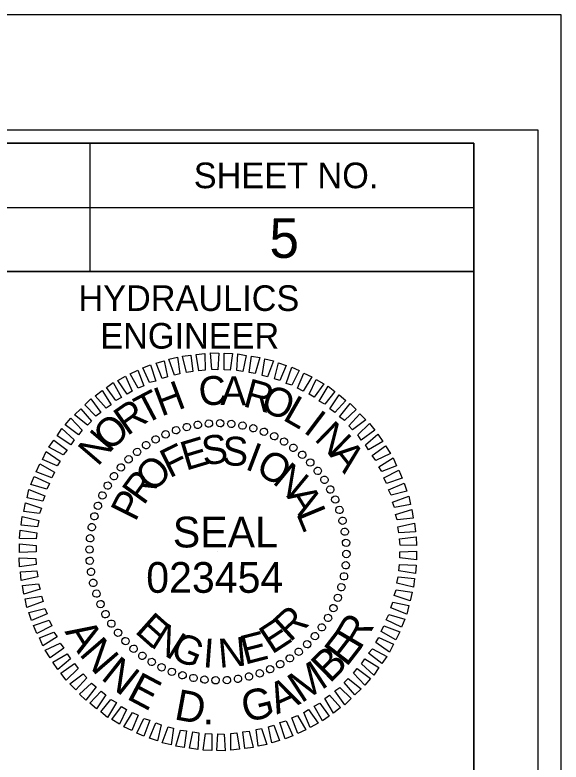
# Model space of a CAD drawing. Extents: x 574125 to 576234, y -56630 to -55530.
# Drawn here: x 575917.2 to 576023.8, y -55675.6 to -55529.8 of the extents above; entities that cross this region are included whole.
import ezdxf

# ---------------------------------------------------------------- set-up
doc = ezdxf.new("R2010")
doc.units = 0
for name, color, linetype in [('Sheet Data Field CELL', 7, 'Continuous'), ('Sheet Plot Border Inside CELL', 7, 'Continuous'), ('Sheet Plot Border Outside CELL', 7, 'Continuous'), ('Sheet Professional Seal CELL', 7, 'Continuous'), ('Sheet Profile CELL', 7, 'Continuous')]:
    doc.layers.add(name, color=color, linetype=linetype)

msp = doc.modelspace()

# ---------------------------------------------------------------- linework, layer by layer
at = {"layer": 'Sheet Plot Border Inside CELL'}
msp.add_lwpolyline([(576019.31, -55552.3), (574352.81, -55552.3), (574352.81, -56607.4), (576019.31, -56607.4)], close=True, dxfattribs=at)
at = {"layer": 'Sheet Plot Border Outside CELL'}
msp.add_lwpolyline([(576023.81, -55529.85), (574339.81, -55529.85), (574339.81, -56629.85), (576023.81, -56629.85)], close=True, dxfattribs=at)
at = {"layer": 'Sheet Professional Seal CELL'}
for p, q in [((575950.72, -55610.24), (575950.72, -55610.24)), ((575952.92, -55609.84), (575952.92, -55609.84)), ((575955.07, -55609.54), (575955.07, -55609.54)), ((575957.27, -55609.49), (575957.27, -55609.49)), ((575959.47, -55609.64), (575959.47, -55609.64)), ((575961.62, -55609.99), (575961.62, -55609.99)), ((575946.62, -55611.64), (575946.62, -55611.64)), ((575948.62, -55610.84), (575948.62, -55610.84)), ((575963.72, -55610.44), (575963.72, -55610.44)), ((575965.82, -55611.14), (575965.82, -55611.14)), ((575944.67, -55612.64), (575944.67, -55612.64)), ((575967.82, -55612.04), (575967.82, -55612.04)), ((575969.77, -55613.04), (575969.77, -55613.04)), ((575942.77, -55613.79), (575942.77, -55613.79)), ((575971.57, -55614.29), (575971.57, -55614.29)), ((575941.02, -55615.04), (575941.02, -55615.04)), ((575973.32, -55615.64), (575973.32, -55615.64)), ((575939.37, -55616.54), (575939.37, -55616.54)), ((575974.87, -55617.14), (575974.87, -55617.14)), ((575937.87, -55618.09), (575937.87, -55618.09)), ((575976.37, -55618.79), (575976.37, -55618.79)), ((575936.52, -55619.84), (575936.52, -55619.84)), ((575977.62, -55620.54), (575977.62, -55620.54)), ((575935.27, -55621.64), (575935.27, -55621.64)), ((575978.77, -55622.44), (575978.77, -55622.44)), ((575934.27, -55623.59), (575934.27, -55623.59)), ((575979.77, -55624.39), (575979.77, -55624.39)), ((575933.37, -55625.59), (575933.37, -55625.59)), ((575980.57, -55626.39), (575980.57, -55626.39)), ((575932.67, -55627.69), (575932.67, -55627.69)), ((575981.17, -55628.49), (575981.17, -55628.49)), ((575932.22, -55629.79), (575932.22, -55629.79)), ((575981.57, -55630.69), (575981.57, -55630.69)), ((575931.87, -55631.94), (575931.87, -55631.94)), ((575981.87, -55632.84), (575981.87, -55632.84)), ((575931.72, -55634.14), (575931.72, -55634.14)), ((575956.82, -55634.59), (575956.82, -55634.59)), ((575981.92, -55635.04), (575981.92, -55635.04)), ((575931.77, -55636.34), (575931.77, -55636.34)), ((575981.77, -55637.24), (575981.77, -55637.24)), ((575932.07, -55638.49), (575932.07, -55638.49)), ((575981.42, -55639.39), (575981.42, -55639.39)), ((575932.47, -55640.69), (575932.47, -55640.69)), ((575980.97, -55641.49), (575980.97, -55641.49)), ((575933.07, -55642.79), (575933.07, -55642.79)), ((575980.27, -55643.59), (575980.27, -55643.59)), ((575933.87, -55644.79), (575933.87, -55644.79)), ((575934.87, -55646.74), (575934.87, -55646.74)), ((575979.37, -55645.59), (575979.37, -55645.59)), ((575978.37, -55647.54), (575978.37, -55647.54)), ((575936.02, -55648.64), (575936.02, -55648.64)), ((575977.12, -55649.34), (575977.12, -55649.34)), ((575937.27, -55650.39), (575937.27, -55650.39)), ((575975.77, -55651.09), (575975.77, -55651.09)), ((575938.77, -55652.04), (575938.77, -55652.04)), ((575974.27, -55652.64), (575974.27, -55652.64)), ((575940.32, -55653.54), (575940.32, -55653.54)), ((575972.62, -55654.14), (575972.62, -55654.14)), ((575942.07, -55654.89), (575942.07, -55654.89)), ((575970.87, -55655.39), (575970.87, -55655.39)), ((575943.87, -55656.14), (575943.87, -55656.14)), ((575968.97, -55656.54), (575968.97, -55656.54)), ((575945.82, -55657.14), (575945.82, -55657.14)), ((575947.82, -55658.04), (575947.82, -55658.04)), ((575965.02, -55658.34), (575965.02, -55658.34)), ((575967.02, -55657.54), (575967.02, -55657.54)), ((575949.92, -55658.74), (575949.92, -55658.74)), ((575952.02, -55659.19), (575952.02, -55659.19)), ((575954.17, -55659.54), (575954.17, -55659.54)), ((575956.37, -55659.69), (575956.37, -55659.69)), ((575958.57, -55659.64), (575958.57, -55659.64)), ((575960.72, -55659.34), (575960.72, -55659.34)), ((575962.92, -55658.94), (575962.92, -55658.94))]:
    msp.add_line(p, q, dxfattribs=at)
for points in [[(575955.62, -55599.04), (575955.37, -55595.79), (575957.02, -55595.84), (575956.82, -55599.09)], [(575958.02, -55599.09), (575958.02, -55595.84), (575959.67, -55595.89), (575959.22, -55599.14)], [(575948.32, -55600.14), (575947.27, -55596.99), (575948.97, -55596.64), (575949.37, -55599.89)], [(575950.72, -55599.59), (575949.92, -55596.39), (575951.57, -55596.24), (575951.92, -55599.44)], [(575953.12, -55599.29), (575952.57, -55596.09), (575954.27, -55595.89), (575954.32, -55599.14)], [(575960.52, -55599.24), (575960.72, -55595.99), (575962.37, -55596.29), (575961.72, -55599.44)], [(575962.92, -55599.64), (575963.37, -55596.44), (575965.02, -55596.69), (575964.12, -55599.79)], [(575965.47, -55600.19), (575965.97, -55596.94), (575967.67, -55597.34), (575966.52, -55600.44)], [(575943.47, -55601.59), (575942.17, -55598.69), (575943.67, -55598.09), (575944.72, -55601.29)], [(575945.92, -55600.79), (575944.77, -55597.79), (575946.32, -55597.34), (575946.97, -55600.44)], [(575967.87, -55600.84), (575968.62, -55597.74), (575970.17, -55598.24), (575968.92, -55601.19)], [(575970.12, -55601.74), (575971.27, -55598.59), (575972.67, -55599.19), (575971.27, -55602.09)], [(575941.27, -55602.64), (575939.67, -55599.84), (575941.22, -55599.14), (575942.37, -55602.19)], [(575972.37, -55602.69), (575973.62, -55599.74), (575975.17, -55600.44), (575973.47, -55603.24)], [(575936.92, -55605.09), (575935.07, -55602.54), (575936.37, -55601.59), (575938.02, -55604.49)], [(575939.12, -55603.84), (575937.27, -55601.14), (575938.82, -55600.34), (575940.07, -55603.24)], [(575974.67, -55603.84), (575976.02, -55600.99), (575977.52, -55601.84), (575975.62, -55604.44)], [(575976.62, -55605.19), (575978.37, -55602.29), (575979.67, -55603.34), (575977.72, -55605.79)], [(575935.02, -55606.59), (575932.87, -55604.19), (575934.22, -55603.14), (575935.97, -55605.94)], [(575978.67, -55606.69), (575980.52, -55603.94), (575981.82, -55605.04), (575979.62, -55607.39)], [(575933.02, -55608.14), (575930.82, -55605.94), (575932.02, -55604.74), (575933.97, -55607.44)], [(575980.57, -55608.24), (575982.62, -55605.64), (575983.82, -55606.84), (575981.52, -55608.99)], [(575931.37, -55609.89), (575928.82, -55607.84), (575930.07, -55606.69), (575932.17, -55609.09)], [(575929.62, -55611.79), (575927.02, -55609.84), (575928.12, -55608.54), (575930.32, -55610.89)], [(575982.37, -55609.99), (575984.52, -55607.64), (575985.72, -55608.84), (575983.12, -55610.79)], [(575984.12, -55611.79), (575986.42, -55609.54), (575987.47, -55610.89), (575984.82, -55612.79)], [(575928.12, -55613.69), (575925.42, -55611.99), (575926.37, -55610.54), (575928.77, -55612.74)], [(575985.62, -55613.74), (575988.07, -55611.64), (575989.02, -55613.09), (575986.22, -55614.69)], [(575926.62, -55615.69), (575923.82, -55614.19), (575924.82, -55612.79), (575927.42, -55614.79)], [(575986.92, -55615.79), (575989.57, -55613.89), (575990.52, -55615.39), (575987.62, -55616.79)], [(575925.42, -55617.84), (575922.57, -55616.59), (575923.32, -55615.04), (575926.02, -55616.89)], [(575988.22, -55617.99), (575991.02, -55616.24), (575991.67, -55617.79), (575988.82, -55618.94)], [(575924.42, -55620.14), (575921.32, -55618.99), (575922.07, -55617.44), (575924.92, -55619.04)], [(575989.22, -55620.14), (575992.17, -55618.64), (575992.82, -55620.24), (575989.72, -55621.24)], [(575923.42, -55622.34), (575920.32, -55621.44), (575920.97, -55619.89), (575923.97, -55621.29)], [(575990.12, -55622.49), (575993.17, -55621.19), (575993.72, -55622.74), (575990.62, -55623.54)], [(575922.67, -55624.74), (575919.57, -55624.09), (575919.92, -55622.44), (575923.07, -55623.69)], [(575990.92, -55624.89), (575994.12, -55623.74), (575994.42, -55625.39), (575991.27, -55625.94)], [(575922.02, -55627.14), (575918.92, -55626.74), (575919.27, -55625.04), (575922.42, -55626.09)], [(575991.52, -55627.29), (575994.67, -55626.34), (575994.97, -55628.04), (575991.82, -55628.34)], [(575921.62, -55629.69), (575918.42, -55629.39), (575918.62, -55627.69), (575921.87, -55628.49)], [(575991.97, -55629.69), (575995.22, -55628.99), (575995.37, -55630.69), (575992.17, -55630.89)], [(575921.37, -55632.09), (575918.12, -55631.99), (575918.22, -55630.34), (575921.47, -55630.89)], [(575992.27, -55632.09), (575995.52, -55631.69), (575995.62, -55633.39), (575992.37, -55633.29)], [(575921.32, -55634.59), (575918.07, -55634.74), (575918.07, -55633.04), (575921.32, -55633.39)], [(575992.32, -55634.59), (575995.57, -55634.44), (575995.57, -55636.14), (575992.32, -55635.79)], [(575921.37, -55637.09), (575918.12, -55637.49), (575918.02, -55635.79), (575921.27, -55635.89)], [(575992.27, -55637.09), (575995.52, -55637.19), (575995.42, -55638.84), (575992.17, -55638.29)], [(575921.67, -55639.49), (575918.42, -55640.19), (575918.27, -55638.49), (575921.47, -55638.29)], [(575992.02, -55639.49), (575995.22, -55639.79), (575995.02, -55641.49), (575991.77, -55640.69)], [(575922.12, -55641.89), (575918.97, -55642.84), (575918.67, -55641.14), (575921.82, -55640.84)], [(575991.62, -55642.04), (575994.72, -55642.44), (575994.37, -55644.14), (575991.22, -55643.09)], [(575922.72, -55644.29), (575919.52, -55645.44), (575919.22, -55643.79), (575922.37, -55643.24)], [(575990.97, -55644.44), (575994.07, -55645.09), (575993.72, -55646.74), (575990.57, -55645.49)], [(575923.52, -55646.69), (575920.47, -55647.99), (575919.92, -55646.44), (575923.02, -55645.64)], [(575990.22, -55646.84), (575993.32, -55647.74), (575992.67, -55649.29), (575989.67, -55647.89)], [(575924.42, -55649.04), (575921.47, -55650.54), (575920.82, -55648.94), (575923.92, -55647.94)], [(575989.22, -55649.04), (575992.32, -55650.19), (575991.57, -55651.74), (575988.72, -55650.14)], [(575925.42, -55651.19), (575922.62, -55652.94), (575921.97, -55651.39), (575924.82, -55650.24)], [(575926.72, -55653.39), (575924.07, -55655.29), (575923.12, -55653.79), (575926.02, -55652.39)], [(575988.22, -55651.34), (575991.07, -55652.59), (575990.32, -55654.14), (575987.62, -55652.29)], [(575987.02, -55653.49), (575989.82, -55654.99), (575988.82, -55656.39), (575986.22, -55654.39)], [(575928.02, -55655.44), (575925.57, -55657.54), (575924.62, -55656.09), (575927.42, -55654.49)], [(575985.52, -55655.49), (575988.22, -55657.19), (575987.27, -55658.64), (575984.87, -55656.44)], [(575929.52, -55657.39), (575927.22, -55659.64), (575926.17, -55658.29), (575928.82, -55656.39)], [(575931.27, -55659.19), (575929.12, -55661.54), (575927.92, -55660.34), (575930.52, -55658.39)], [(575984.02, -55657.39), (575986.62, -55659.34), (575985.52, -55660.64), (575983.32, -55658.29)], [(575982.27, -55659.29), (575984.82, -55661.34), (575983.57, -55662.49), (575981.47, -55660.09)], [(575933.07, -55660.94), (575931.02, -55663.54), (575929.82, -55662.34), (575932.12, -55660.19)], [(575980.62, -55661.04), (575982.82, -55663.24), (575981.62, -55664.44), (575979.67, -55661.74)], [(575934.97, -55662.49), (575933.12, -55665.24), (575931.82, -55664.14), (575934.02, -55661.79)], [(575978.62, -55662.59), (575980.77, -55664.99), (575979.42, -55666.04), (575977.67, -55663.24)], [(575937.02, -55663.99), (575935.27, -55666.89), (575933.97, -55665.84), (575935.92, -55663.39)], [(575976.72, -55664.09), (575978.57, -55666.64), (575977.27, -55667.59), (575975.62, -55664.69)], [(575938.97, -55665.34), (575937.62, -55668.19), (575936.12, -55667.34), (575938.02, -55664.74)], [(575974.52, -55665.34), (575976.37, -55668.04), (575974.82, -55668.84), (575973.57, -55665.94)], [(575941.27, -55666.49), (575940.02, -55669.44), (575938.47, -55668.74), (575940.17, -55665.94)], [(575943.52, -55667.44), (575942.37, -55670.59), (575940.97, -55669.99), (575942.37, -55667.09)], [(575972.37, -55666.54), (575973.97, -55669.34), (575972.42, -55670.04), (575971.27, -55666.99)], [(575945.77, -55668.34), (575945.02, -55671.44), (575943.47, -55670.94), (575944.72, -55667.99)], [(575967.72, -55668.39), (575968.87, -55671.39), (575967.32, -55671.84), (575966.67, -55668.74)], [(575970.17, -55667.59), (575971.47, -55670.49), (575969.97, -55671.09), (575968.92, -55667.89)], [(575948.17, -55668.99), (575947.67, -55672.24), (575945.97, -55671.84), (575947.12, -55668.74)], [(575950.72, -55669.54), (575950.27, -55672.74), (575948.62, -55672.49), (575949.52, -55669.39)], [(575953.12, -55669.94), (575952.92, -55673.19), (575951.27, -55672.89), (575951.92, -55669.74)], [(575955.62, -55670.09), (575955.62, -55673.34), (575953.97, -55673.29), (575954.42, -55670.04)], [(575958.02, -55670.14), (575958.27, -55673.39), (575956.62, -55673.34), (575956.82, -55670.09)], [(575960.52, -55669.89), (575961.07, -55673.09), (575959.37, -55673.29), (575959.32, -55670.04)], [(575962.92, -55669.59), (575963.72, -55672.79), (575962.07, -55672.94), (575961.72, -55669.74)], [(575965.32, -55669.04), (575966.37, -55672.19), (575964.67, -55672.54), (575964.27, -55669.29)]]:
    msp.add_lwpolyline(points, close=True, dxfattribs=at)
for centre, major_axis in [((575955.07, -55609.57), (-0.05, 0.718)), ((575957.26, -55609.51), (0.013, 0.72)), ((575959.44, -55609.64), (0.075, 0.716)), ((575948.66, -55610.87), (-0.234, 0.681)), ((575950.76, -55610.25), (-0.174, 0.699)), ((575952.9, -55609.81), (-0.113, 0.711)), ((575961.61, -55609.97), (0.137, 0.707)), ((575963.74, -55610.48), (0.198, 0.692)), ((575965.81, -55611.17), (0.258, 0.672)), ((575944.66, -55612.65), (-0.349, 0.63)), ((575946.62, -55611.67), (-0.293, 0.658)), ((575967.82, -55612.04), (0.316, 0.647)), ((575942.8, -55613.79), (-0.403, 0.597)), ((575969.74, -55613.09), (0.371, 0.617)), ((575941.04, -55615.1), (-0.453, 0.56)), ((575971.56, -55614.3), (0.423, 0.582)), ((575939.4, -55616.55), (-0.5, 0.518)), ((575973.28, -55615.66), (0.472, 0.543)), ((575937.89, -55618.13), (-0.543, 0.472)), ((575974.86, -55617.16), (0.518, 0.5)), ((575936.53, -55619.84), (-0.582, 0.423)), ((575976.31, -55618.8), (0.56, 0.453)), ((575977.61, -55620.56), (0.597, 0.403)), ((575935.32, -55621.67), (-0.617, 0.371)), ((575978.76, -55622.43), (0.63, 0.349)), ((575934.28, -55623.59), (-0.647, 0.316)), ((575933.41, -55625.6), (-0.672, 0.258)), ((575979.73, -55624.39), (0.658, 0.293)), ((575980.54, -55626.42), (0.681, 0.234)), ((575932.71, -55627.67), (-0.692, 0.198)), ((575981.16, -55628.52), (0.699, 0.174)), ((575932.2, -55629.8), (-0.707, 0.137)), ((575981.59, -55630.66), (0.711, 0.113)), ((575931.88, -55631.96), (-0.716, 0.075)), ((575981.84, -55632.84), (0.718, 0.05)), ((575931.75, -55634.15), (-0.72, 0.013)), ((575981.9, -55635.02), (0.72, -0.013)), ((575931.8, -55636.34), (-0.718, -0.05)), ((575981.77, -55637.21), (0.716, -0.075)), ((575932.05, -55638.51), (-0.711, -0.113)), ((575981.44, -55639.37), (0.707, -0.137)), ((575932.49, -55640.65), (-0.699, -0.174)), ((575980.93, -55641.5), (0.692, -0.198)), ((575933.11, -55642.75), (-0.681, -0.234)), ((575980.24, -55643.57), (0.672, -0.258)), ((575933.91, -55644.79), (-0.658, -0.293)), ((575979.36, -55645.58), (0.647, -0.316)), ((575934.89, -55646.75), (-0.63, -0.349)), ((575978.32, -55647.5), (0.617, -0.371)), ((575936.03, -55648.61), (-0.597, -0.403)), ((575937.33, -55650.37), (-0.56, -0.453)), ((575977.11, -55649.33), (0.582, -0.423)), ((575938.78, -55652.01), (-0.518, -0.5)), ((575975.75, -55651.04), (0.543, -0.472)), ((575974.24, -55652.63), (0.5, -0.518)), ((575940.37, -55653.51), (-0.472, -0.543)), ((575942.08, -55654.88), (-0.423, -0.582)), ((575972.61, -55654.08), (0.453, -0.56)), ((575943.91, -55656.08), (-0.371, -0.617)), ((575970.85, -55655.38), (0.403, -0.597)), ((575945.83, -55657.13), (-0.316, -0.647)), ((575967.02, -55657.5), (0.293, -0.658)), ((575968.98, -55656.52), (0.349, -0.63)), ((575947.83, -55658), (-0.258, -0.672)), ((575949.91, -55658.69), (-0.198, -0.692)), ((575952.04, -55659.21), (-0.137, -0.707)), ((575962.89, -55658.92), (0.174, -0.699)), ((575964.99, -55658.3), (0.234, -0.681)), ((575954.2, -55659.53), (-0.075, -0.716)), ((575956.38, -55659.66), (-0.013, -0.72)), ((575958.57, -55659.61), (0.05, -0.718)), ((575960.75, -55659.36), (0.113, -0.711))]:
    msp.add_ellipse(centre, major_axis=major_axis, ratio=0.999708, dxfattribs=at)
at = {"layer": 'Sheet Profile CELL'}
for p, q in [((576023.81, -55529.85), (574339.81, -55529.85)), ((575931.81, -55554.9), (575931.81, -55579.9)), ((575806.76, -55567.4), (576006.81, -55567.4))]:
    msp.add_line(p, q, dxfattribs=at)
for points in [[(576006.81, -55554.85), (574506.81, -55554.85), (574506.81, -56604.85), (576006.81, -56604.85)], [(575806.76, -55554.85), (576006.81, -55554.85), (576006.81, -55579.9), (575806.76, -55579.9)], [(575906.81, -55579.9), (576006.81, -55579.9), (576006.81, -55692.4), (575906.81, -55692.4)]]:
    msp.add_lwpolyline(points, close=True, dxfattribs=at)

# ---------------------------------------------------------------- texts
at = {"layer": 'Sheet Data Field CELL'}
msp.add_text('5', height=7.75, dxfattribs=at).set_placement((575966.89, -55577.25))
at = {"layer": 'Sheet Professional Seal CELL'}
for s, height, rotation, p in [('C', 5.64, 6.2199, (575953.37, -55606.24)), ('H', 5.64, 20.6195, (575945.77, -55608.24)), ('A', 5.64, 359.0203, (575957.32, -55605.94)), ('R', 5.64, 344.6211, (575961.52, -55606.14)), ('T', 5.64, 27.8198, (575942.52, -55609.89)), ('O', 5.64, 337.4212, (575964.87, -55606.89)), ('L', 5.64, 330.2209, (575969.27, -55608.74)), ('R', 5.64, 35.0205, (575939.12, -55612.09)), ('I', 5.64, 323.0201, (575973.32, -55611.14)), ('O', 5.64, 42.2217, (575935.67, -55615.19)), ('N', 5.64, 315.8189, (575975.47, -55612.69)), ('N', 5.64, 49.4235, (575933.37, -55618.09)), ('S', 5.64, 7.2556, (575954.02, -55617.74)), ('F', 5.64, 25.967, (575947.37, -55620.29)), ('E', 5.64, 16.6111, (575950.57, -55618.79)), ('S', 5.64, 357.9004, (575957.62, -55617.69)), ('I', 5.64, 339.1896, (575961.92, -55618.39)), ('A', 5.64, 308.6172, (575978.42, -55615.64)), ('O', 5.64, 44.6812, (575944.07, -55623.24)), ('O', 5.64, 329.8335, (575963.92, -55619.09)), ('N', 5.64, 320.4766, (575967.27, -55621.09)), ('R', 5.64, 54.0397, (575942.32, -55625.69)), ('P', 5.64, 63.3989, (575940.72, -55628.89)), ('A', 5.64, 301.7603, (575970.12, -55623.69)), ('L', 5.64, 292.4008, (575972.07, -55627.14)), ('SEAL', 5.998, 360, (575948.02, -55633.74)), ('E', 5.64, 318.2769, (575940.42, -55650.24)), ('R', 5.64, 42.4814, (575970.92, -55652.34)), ('E', 5.64, 33.1241, (575967.37, -55654.69)), ('R', 6, 59.4866, (575984.54, -55653.94)), ('A', 6, 301.8734, (575926.83, -55650.17)), ('N', 5.64, 327.634, (575943.42, -55652.94)), ('E', 6, 52.3773, (575981.93, -55657.22)), ('N', 6, 310.7137, (575929.58, -55654.6)), ('G', 5.64, 336.9902, (575947.22, -55655.19)), ('N', 5.64, 5.0564, (575957.12, -55657.24)), ('E', 5.64, 14.4118, (575962.07, -55656.64)), ('I', 5.64, 355.7012, (575953.77, -55657.09)), ('B', 6, 44.6806, (575978.67, -55660.38)), ('N', 6, 321.4396, (575933.78, -55659.32)), ('M', 6, 33.1512, (575973.08, -55664.22)), ('E', 6, 332.1654, (575938.79, -55663.17)), ('A', 6, 24.3108, (575968.33, -55666.37)), ('G', 6, 13.585, (575962.21, -55667.95)), ('D', 6, 349.4751, (575948.11, -55667.24)), ('.', 6, 359.3509, (575953.84, -55668.26))]:
    msp.add_text(s, height=height, rotation=rotation, dxfattribs=at).set_placement(p)
msp.add_text('023454', height=5.998, dxfattribs=at).set_placement((575942.83, -55642.59))
at = {"layer": 'Sheet Profile CELL'}
for s, p in [('SHEET NO.', (575952.11, -55563.65)), ('HYDRAULICS', (575929.61, -55587.6)), ('ENGINEER', (575933.86, -55594.95))]:
    msp.add_text(s, height=5, rotation=360, dxfattribs=at).set_placement(p)

doc.saveas('drawing.dxf')
